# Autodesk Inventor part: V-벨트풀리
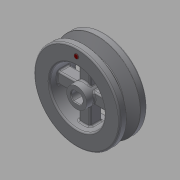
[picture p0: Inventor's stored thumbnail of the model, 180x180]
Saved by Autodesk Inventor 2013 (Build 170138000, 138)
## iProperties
Created: 2018-01
Part Number: V-벨트풀리
Material: 스테인리스강
Document SubType Name: Modeling
Designer: mduedu
Density: 8.08 g/cm^3
Mass: 218.724 g
Surface Area: 130.785 cm^2
Volume: 27.0698 cm^3
Author: mduedu
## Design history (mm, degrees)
sketch "스케치1"
  geometry: C1 r 30 at (0, 0); 1 further point
  constraints: 1 centre point, 1 coincident
  dimensions: "d0" = 60 diameter of C1
extrude "돌출1" new body sketch "스케치1" stored distance "d1" = 19; taper "d2" = 0 deg
sketch "스케치2"
  geometry: L1 (30, -9.5)-(-30, -9.5) reference; L2 (-30, -9.5)-(-30, 9.5) reference; L3 (-30, 9.5)-(30, 9.5) reference; L4 (30, 9.5)-(30, -9.5) reference; L5 (-30, 0)-(30, 0); L6 (30, 4.825)-(21, 2.074); L7 (21, 2.074)-(21, -2.074); L8 (21, -2.074)-(30, -4.825); L9 (30, -4.825)-(30, 4.825); L10 (27.3, 9.5)-(27.3, -9.5); L11 (0, -13.3)-(0, 13.3) reference; 4 further points
  constraints: 12 end point, 9 point on line, 3 midpoint, 2 perpendicular, 1 collinear, 1 symmetric about line
  dimensions: "d3" = 34 deg angle of L8 L6; "d4" = 2.7 distance between parallel lines of L10 L4; "d5" = 6.3 distance between parallel lines of L7 L10; "d6" = 8 distance of point (27.3, -4) point (27.3, 4)
revolve "회전1" sketch "스케치2" stored, may be unused: angle "d7" = 90 deg
fillet "모깎기1" dims "d8" = 0.2
fillet "모깎기2" dims "d9" = 0.5
fillet "모깎기3" dims "d10" = 1
sketch "스케치3"
  geometry: C1 r 19 at (0, 0); 1 further point
  constraints: 1 centre point, 1 coincident
  dimensions: "d11" = 38 diameter of C1
extrude "돌출2" cut sketch "스케치3" stored distance "d12" = 19; taper "d13" = 0 deg
sketch "스케치4"
  geometry: C1 r 7 at (0, 0); 1 further point
  constraints: 1 centre point, 1 coincident
  dimensions: "d14" = 14 diameter of C1
extrude "돌출3" join sketch "스케치4" stored distance "d15" = 19; taper "d16" = 0 deg
sketch "스케치5"
  geometry: L1 (0, 7)-(0, 19); L2 (4, 5.745)-(4, 18.574); L3 (-4, 5.745)-(-4, 18.574); C1 r 21 at (0, 0) reference; A1 r 19 centre (0, 0) between (0, 19) and (-4, 18.574) reference; A2 r 7 centre (0, 0) between (0, 7) and (-4, 5.745) reference; 1 further point
  constraints: 6 end point, 6 point on circle, 2 parallel, 1 point on line, 1 vertical, 1 other
  dimensions: "d17" = 8 distance between parallel lines of L2 L3
extrude "돌출4" join sketch "스케치5" stored distance "d18" = 8; taper "d19" = 0 deg
fillet "모깎기4" dims "d20" = 1
fillet "모깎기5" dims "d24" = 1
fillet "모깎기6" dims "d25" = 1
hole "구멍1" diameter "d28" = 8; stored, may be unused: countersink angle "d32" = 90 deg, drill point angle "d34" = 118 deg; dims "d26" = 10, "d27" = 10, "d29" = 6, "d30" = 4, "d31" = 2, "d33" = 8
sketch "스케치6"
  geometry: L1 (-2.332, -3.25)-(2.332, -3.25); L2 (2.332, 3.25)-(-2.332, 3.25); L3 (-2.332, -3.25)-(2.332, 3.25); L4 (2.332, -3.25)-(-2.332, 3.25); A1 r 4 centre (0, 0) between (2.332, 3.25) and (-2.332, 3.25) reference; A2 r 4 centre (0, 0) between (2.332, 3.25) and (-2.332, 3.25); A3 r 4 centre (0, 0) between (-2.332, -3.25) and (2.332, -3.25); 1 further point
  constraints: 8 end point, 7 point on circle, 2 centre point, 2 coincident, 2 midpoint, 1 horizontal, 1 parallel
  dimensions: "d35" = 6.5 distance of L1.end L2.start
extrude "돌출5" join sketch "스케치6" stored distance "d37" = 8; taper "d38" = 0 deg
chamfer "모따기1" distance "d39" = 0.5; stored, may be unused: second distance "d40" = 2, angle "d41" = 45 deg
chamfer "모따기2" distance "d42" = 0.5; stored, may be unused: second distance "d43" = 2, angle "d44" = 45 deg
sketch "스케치7" dims "d45" = 50
  geometry: C1 r 1.5 at (0, 25); 2 further points
  constraints: 2 vertical alignment, 1 centre point, 1 coincident, 2 other
  dimensions: "d46" = 3 diameter of C1
extrude "돌출6" join sketch "스케치7" distance "d47" = 0.5; taper "d48" = 0 deg
fillet "모깎기7" dims "d49" = 0.1
node "솔리드1"
pattern_circular "원형 패턴1" dims angle "d22" = 360 deg
node "절단 모서리 투영1"
node "절단 모서리 투영2"
